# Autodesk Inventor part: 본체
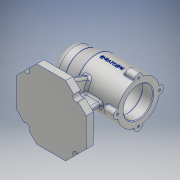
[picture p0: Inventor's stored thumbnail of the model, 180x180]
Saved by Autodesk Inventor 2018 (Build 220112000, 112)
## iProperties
Created: 2021-01
Part Number: 본체
Material: 알루미늄 6061
Document SubType Name: Modeling
Designer: home
Density: 2.7 g/cm^3
Appearance: 알루미늄 - 평지
Mass: 629.962 g
Surface Area: 613.777 cm^2
Volume: 233.319 cm^3
Author: home
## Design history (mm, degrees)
sketch "스케치1"
  geometry: L1 (20.711, -50)-(-20.711, -50); L2 (-20.711, -50)-(-50, -20.711); L3 (-50, -20.711)-(-50, 20.711); L4 (-50, 20.711)-(-20.711, 50); L5 (-20.711, 50)-(20.711, 50); L6 (20.711, 50)-(50, 20.711); L7 (50, 20.711)-(50, -20.711); L8 (50, -20.711)-(20.711, -50); 2 further points
  constraints: 16 end point, 2 coincident, 1 horizontal, 17 other
  dimensions: "d0" = 50 distance from line of L1 point (0, 0)
extrude "돌출1" new body sketch "스케치1" distance "d1" = 10; taper "d2" = 0 deg
sketch "스케치2"
  geometry: L1 (-109.793, 75)-(75.589, 75); L2 (20.711, 0)-(-20.711, 0) reference; L3 (-44, 75)-(-44, 82.5); L4 (-41, 85.5)-(-41, 85.5); L5 (-41, 85.5)-(-41, 90.7); L6 (-40.7, 91)-(-37, 91); L7 (-37, 91)-(-37, 92.2); L8 (-36.7, 92.5)-(-19, 92.5); L9 (-19, 92.5)-(-19, 95.7); L10 (-18.7, 96)-(-7, 96); L11 (-7, 96)-(-7, 96); L12 (-4, 99)-(32, 99); L13 (35, 96)-(35, 96); L14 (35, 96)-(50, 96); L15 (50, 96)-(50, 105); L16 (50, 105)-(35, 105); L17 (-10, 105)-(35, 105); L18 (50, 0)-(50, 10) reference; L19 (-50, 100)-(-30, 100); L20 (-50, 100)-(-50, 75); L21 (-30, 100)-(-10, 105); A1 r 0.3 centre (-40.7, 90.7) between (-40.7, 91) and (-41, 90.7); A2 r 0.3 centre (-36.7, 92.2) between (-36.7, 92.5) and (-37, 92.2); A3 r 0.3 centre (-18.7, 95.7) between (-18.7, 96) and (-19, 95.7); A4 r 3 centre (-41, 82.5) between (-41, 85.5) and (-44, 82.5); A5 r 3 centre (-4, 96) between (-4, 99) and (-7, 96); A6 r 3 centre (32, 96) between (35, 96) and (32, 99); 7 further points
  constraints: 38 end point, 15 point on line, 13 perpendicular, 12 point on circle, 12 tangent, 6 centre point, 4 equal radius, 4 horizontal, 1 collinear, 1 vertical
  dimensions: "d4" = 75 distance between parallel lines of L2 L1; "d5" = 42 diameter of L14 L1; "d6" = 48 diameter of L12 L1; "d7" = 42 diameter of L10 L1; "d8" = 35 diameter of L8 L1; "d9" = 32 diameter of L6 L1; "d10" = 21 diameter of L4 L1; "d11" = 60 diameter of L16 L1; "d15" = 3 distance of point (-44, 85.5) L4.end; "d16" = 4 distance of point (-41, 91) L6.end; "d17" = 18 distance of point (-37, 92.5) L8.end; "d18" = 12 distance of point (-19, 96) L10.end; "d19" = 42 distance of point (-7, 99) point (35, 99); "d20" = 15 distance of L13.end L14.end; "d22" = 0.3 radius of A1; "d23" = 3 radius of A4; "d71" = 50 diameter of L19 L1; "d72" = 100 distance between parallel lines of L15 L20; "d73" = 20 distance of L19.start L19.end; "d74" = 40 distance from line of L20 L17.start
revolve "회전1" sketch "스케치2" stored, may be unused: angle "d24" = 90 deg
sketch "스케치3"
  geometry: L1 (-27, 10)-(-19.023, 51.036); L2 (-19.023, 51.036)-(-4.728, 48.257); L3 (-4.728, 48.257)-(27, 48.257); L4 (-10, 45)-(50, 45) reference; L5 (27, 48.257)-(27, 10); L6 (27, 10)-(-27, 10); L7 (50, 0)-(50, 10) reference; L8 (-50, 0)-(-50, 10) reference; L9 (20.711, 10)-(-20.711, 10) reference; L10 (-20.711, 10)-(-50, 10) reference; 1 further point
  constraints: 10 end point, 3 perpendicular, 1 collinear, 1 parallel
  dimensions: "d26" = 23 distance between parallel lines of L7 L5; "d27" = 23 distance from line of L8 L1.start; "d28" = 101 deg angle of L10 L1
extrude "돌출2" join sketch "스케치3" stored distance "d29" = 8; taper "d30" = 0 deg
sketch "스케치4"
  geometry: L1 (10, 35)-(52.293, 19.606); L2 (0, 50)-(10, 50) reference; L3 (52.293, -19.606)-(10, -35); L4 (0, -50)-(10, -50) reference; L5 (10, 20.711)-(10, 50) reference; L6 (10, -50)-(10, -20.711) reference; L7 (10, 35)-(10, -35); L8 (0, 20.711)-(0, -20.711) reference; A1 r 30 centre (75, 0) between (52.293, 19.606) and (52.293, -19.606); A2 r 30 centre (75, 0) between (45.268, -4) and (45.268, 4) reference; 1 further point
  constraints: 6 end point, 2 point on circle, 2 point on line, 1 centre point, 1 concentric, 1 parallel
  dimensions: "d32" = 15 distance from line of L2 L1.start; "d33" = 15 distance from line of L4 L3.end; "d34" = 110 deg angle of L1 L5; "d35" = 110 deg angle of L6 L3
extrude "돌출3" join sketch "스케치4" stored distance "d36" = 8; taper "d37" = 0 deg
sketch "스케치5"
  geometry: C1 r 6 at (0, 30); 2 further points
  constraints: 2 vertical alignment, 1 centre point, 1 other
  dimensions: "d38" = 12 diameter of C1
extrude "돌출4" join sketch "스케치5" distance "d39" = 16; taper "d40" = 0 deg
sketch "스케치6"
  geometry: C1 r 21 at (0, -30) reference; A1 r 30 centre (0, -30) between (29.4, -24.03) and (5.97, -0.6) reference; A2 r 6 centre (0, 0) between (5.97, -0.6) and (-5.97, -0.6) reference; A3 r 30 centre (0, -30) between (-5.97, -0.6) and (-29.4, -24.03) reference; A4 r 6 centre (-30, -30) between (-29.4, -24.03) and (-29.4, -35.97) reference; A5 r 30 centre (0, -30) between (-29.4, -35.97) and (-5.97, -59.4) reference; A6 r 6 centre (0, -60) between (-5.97, -59.4) and (5.97, -59.4) reference; A7 r 30 centre (0, -30) between (5.97, -59.4) and (29.4, -35.97) reference; A8 r 6 centre (30, -30) between (29.4, -35.97) and (29.4, -24.03) reference; 1 further point
hole "구멍1" sketch "스케치6" at (0, 0), (30, -30), (0, -60), (-30, -30) diameter "d44" = 3.242; stored, may be unused: countersink angle "d48" = 90 deg, drill point angle "d50" = 118 deg; dims "d45" = 8, "d46" = 4, "d47" = 2, "d49" = 10
sketch "스케치7" dims "d52" = 100
  geometry: L1 (-20.711, -50)-(-50, -20.711) reference; C1 r 4.5 at (-35.355, -35.355); C2 r 4.5 at (35.355, -35.355); C3 r 4.5 at (35.355, 35.355); C4 r 4.5 at (-35.355, 35.355); 2 further points
  constraints: 4 centre point, 1 coincident, 1 midpoint, 12 other
  dimensions: "d51" = 9 diameter of C1; "d55" = 360 deg dimension on point (0, 0) C1.centre (derived)
extrude "돌출5" cut sketch "스케치7" distance "d57" = 16; taper "d58" = 0 deg
node "작업 평면1"
sketch "스케치8"
  geometry: L1 (50, 80.97)-(50, 104.4) reference; L2 (20.711, 0)-(-20.711, 0) reference; 2 further points
  constraints: 1 other
  dimensions: "d60" = 38 distance from line of L1 point (12, 75); "d61" = 75 distance from line of L2 point (12, 75)
feature "엠보싱1" sketch "스케치8" dims "d0" = 50, "d62" = 0.5, "d63" = 0
fillet "모깎기2" dims "d64" = 3
fillet "모깎기4" dims "d66" = 3
fillet "모깎기5" dims "d67" = 1
fillet "모깎기6" dims "d68" = 3
fillet "모깎기8" dims "d70" = 3
fillet "모깎기9" dims "d75" = 3
fillet "모깎기10" dims "d76" = 10
chamfer "모따기1" distance "d77" = 1; stored, may be unused: second distance "d78" = 2, angle "d79" = 45 deg
node "솔리드1"
pattern_circular "원형 패턴1" dims angle "d42" = 360 deg
node "투영된 루프1"
other parameters: "d59" = 122.5
